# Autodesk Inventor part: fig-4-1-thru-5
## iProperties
Created: 2004-05
Part Number: fig-4-1-thru-5
Document SubType Name: Modeling
Designer: CADCIM Technologies
Manufacturer: Standard
Standards Organization: Custom
Density: 1 g/cm^3
Author: CADCIM Technologies
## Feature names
1. Extrusion1
2. Fillet1
